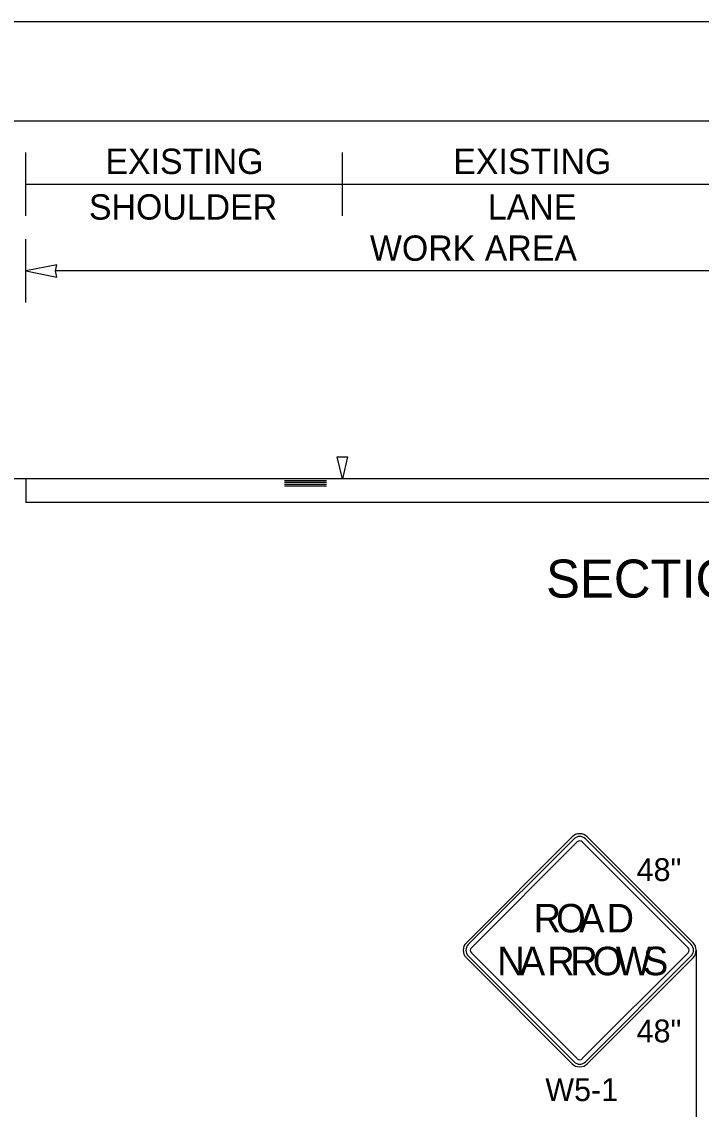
# Model space of a CAD drawing. Extents: x 99999 to 100116, y 99995 to 100013.
# Drawn here: x 100025.445 to 100027.591, y 100007.255 to 100010.687 of the extents above; entities that cross this region are included whole.
import ezdxf

# ---------------------------------------------------------------- set-up
doc = ezdxf.new("R2010")
doc.units = 0
for name, color, linetype in [('SH_GI_PlotLimits', 7, 'Continuous'), ('SH_GI_SheetBorder', 7, 'Continuous'), ('SH_TI_WZSectionCut', 7, 'Continuous'), ('TR_SN_ConstructionSigns', 7, 'Continuous'), ('TR_WZ_WorkZoneDetails', 7, 'Continuous')]:
    doc.layers.add(name, color=color, linetype=linetype)

msp = doc.modelspace()

# ---------------------------------------------------------------- linework, layer by layer
at = {"layer": 'SH_GI_PlotLimits'}
msp.add_lwpolyline([(100019.0625, 99999.6875), (100036.0625, 99999.6875), (100036.0625, 100010.6875), (100019.0625, 100010.6875)], close=True, dxfattribs=at)
at = {"layer": 'SH_GI_SheetBorder'}
msp.add_line((100020, 100010.375), (100035.75, 100010.375), dxfattribs=at)
at = {"layer": 'SH_TI_WZSectionCut'}
for p, q in [((100025.4578, 100010.075), (100025.4578, 100010.275)), ((100026.4578, 100010.075), (100026.4578, 100010.275)), ((100025.4578, 100010.175), (100026.4578, 100010.175)), ((100026.4578, 100010.175), (100027.6578, 100010.175)), ((100025.4578, 100009.801), (100025.4578, 100010.001)), ((100028.264, 100009.901), (100025.5515, 100009.901)), ((100025.4578, 100009.2449), (100025.4578, 100009.1699)), ((100029.8578, 100009.2449), (100025.4578, 100009.2449)), ((100026.2748, 100009.2397), (100026.4078, 100009.2397)), ((100026.2748, 100009.2341), (100026.4078, 100009.2341)), ((100026.2748, 100009.2284), (100026.4078, 100009.2284)), ((100026.2748, 100009.2232), (100026.4078, 100009.2232)), ((100029.8578, 100009.1699), (100025.4578, 100009.1699))]:
    msp.add_line(p, q, dxfattribs=at)
for points in [[(100025.4578, 100009.901), (100025.556, 100009.8817), (100025.5515, 100009.901), (100025.556, 100009.9203)], [(100026.4411, 100009.3147), (100026.4744, 100009.3147), (100026.4578, 100009.2449)]]:
    msp.add_lwpolyline(points, close=True, dxfattribs=at)
msp.add_open_spline([(100025.4578, 100009.2449), (100025.2066, 100009.2449), (100025.0811, 100009.1828), (100024.9556, 100009.1828)], degree=2, dxfattribs=at)
at = {"layer": 'TR_SN_ConstructionSigns'}
for p, q in [((100027.1836, 100008.1149), (100026.8495, 100007.7808)), ((100027.5654, 100007.7808), (100027.2313, 100008.1149)), ((100027.1895, 100008.1089), (100026.8554, 100007.7748)), ((100026.8654, 100007.7649), (100027.1995, 100008.099)), ((100027.2154, 100008.099), (100027.5495, 100007.7649)), ((100027.5594, 100007.7748), (100027.2253, 100008.1089)), ((100026.8554, 100007.739), (100027.1895, 100007.4049)), ((100027.1995, 100007.4149), (100026.8654, 100007.749)), ((100027.5495, 100007.749), (100027.2154, 100007.4149)), ((100027.2253, 100007.4049), (100027.5594, 100007.739)), ((100026.8495, 100007.7331), (100027.1836, 100007.3989)), ((100027.2313, 100007.3989), (100027.5654, 100007.7331))]:
    msp.add_line(p, q, dxfattribs=at)
for centre, radius, start, end in [((100027.2074, 100008.091), 0.0338, 45, 135), ((100027.2074, 100008.091), 0.0253, 45, 135), ((100027.2074, 100008.091), 0.0113, 45, 135), ((100026.8733, 100007.7569), 0.0338, 135, 225), ((100026.8733, 100007.7569), 0.0253, 135, 225), ((100027.5415, 100007.7569), 0.0253, 315, 45), ((100027.5415, 100007.7569), 0.0338, 315, 45), ((100026.8733, 100007.7569), 0.0113, 135, 225), ((100027.5415, 100007.7569), 0.0113, 315, 45), ((100027.2074, 100007.4228), 0.0338, 225, 315), ((100027.2074, 100007.4228), 0.0253, 225, 315), ((100027.2074, 100007.4228), 0.0113, 225, 315)]:
    msp.add_arc(centre, radius, start, end, dxfattribs=at)
at = {"layer": 'TR_WZ_WorkZoneDetails'}
msp.add_line((100027.5753, 100007.7569), (100027.5753, 100004.9891), dxfattribs=at)

# ---------------------------------------------------------------- texts
at = {"layer": 'SH_TI_WZSectionCut'}
for s, height, p in [('EXISTING', 0.08, (100025.7095, 100010.207)), ('EXISTING', 0.08, (100026.808, 100010.207)), ('SHOULDER', 0.08, (100025.6575, 100010.063)), ('LANE', 0.08, (100026.9174, 100010.063)), ('SECTION', 0.12, (100027.1012, 100008.87))]:
    msp.add_text(s, height=height, rotation=360, dxfattribs=at).set_placement(p)
msp.add_text('WORK AREA', height=0.08, dxfattribs=at).set_placement((100026.5449, 100009.933))
at = {"layer": 'TR_SN_ConstructionSigns'}
for s, p in [('48"', (100027.3872, 100007.9755)), ('48"', (100027.3872, 100007.4664)), ('W5-1', (100027.0988, 100007.2811))]:
    msp.add_text(s, height=0.072, rotation=360, dxfattribs=at).set_placement(p)
for s, p in [('R', (100027.0615, 100007.8132)), ('O', (100027.1328, 100007.8132)), ('A', (100027.2055, 100007.8132)), ('D', (100027.2921, 100007.8132)), ('N', (100026.9468, 100007.6782)), ('A', (100027.0181, 100007.6782)), ('R', (100027.1047, 100007.6782)), ('R', (100027.1774, 100007.6782)), ('O', (100027.2487, 100007.6782)), ('W', (100027.3214, 100007.6782)), ('S', (100027.4069, 100007.6782))]:
    msp.add_text(s, height=0.09, dxfattribs=at).set_placement(p)

doc.saveas('drawing.dxf')
